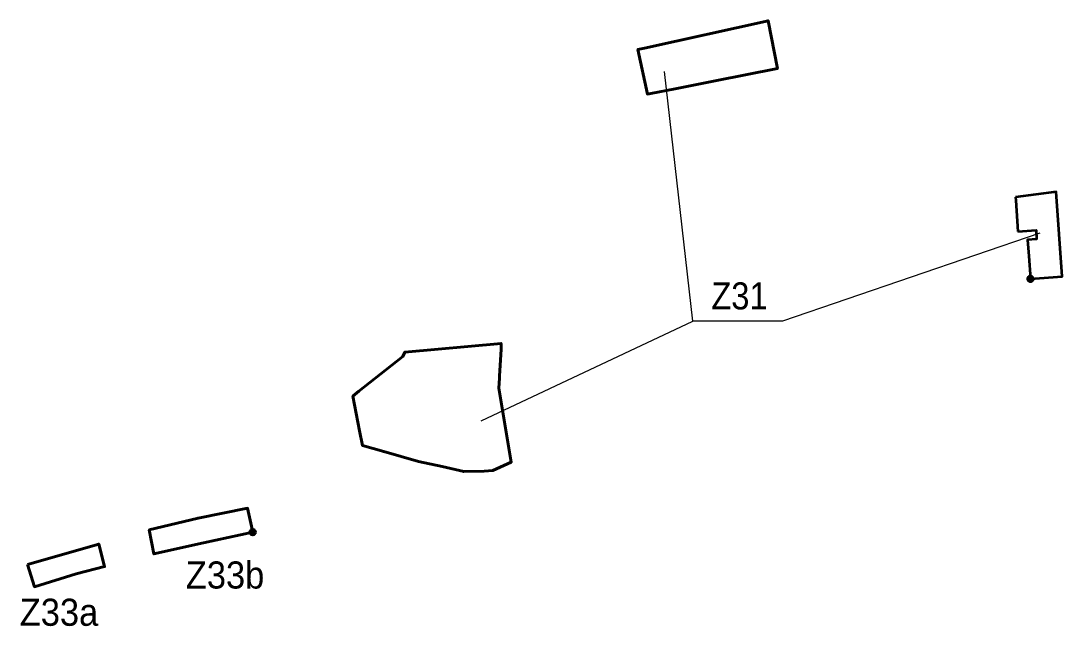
# Model space of a CAD drawing. Extents: x -650277 to -643422, y -1073980 to -1066720.
# Drawn here: x -644344 to -643422, y -1070237 to -1069701 of the extents above; entities that cross this region are included whole.
import ezdxf

# ---------------------------------------------------------------- set-up
doc = ezdxf.new("R2010")
doc.units = 0
doc.header["$LTSCALE"] = 9.6
doc.header["$PDMODE"] = 32
doc.header["$PDSIZE"] = 4.8
for name, color, linetype, lineweight in [('1', 7, 'Continuous', 60), ('3', 7, 'Continuous', 60), ('5', 7, 'Continuous', 60), ('63', 7, 'Continuous', 25), ('8', 7, 'Continuous', 60)]:
    doc.layers.add(name, color=color, linetype=linetype, lineweight=lineweight)

msp = doc.modelspace()

# ---------------------------------------------------------------- linework, layer by layer
at = {"layer": '1', "lineweight": 53}
for points in [[(-643450.3, -1069929.7), (-643422.204, -1069927.68), (-643427.6, -1069852.59), (-643463.51, -1069857.44)], [(-643463.51, -1069857.44), (-643463.31, -1069860.18), (-643461.327, -1069887.84)], [(-643461.327, -1069887.84), (-643445.37, -1069886.7), (-643444.79, -1069894.68), (-643452.77, -1069895.25), (-643451.74, -1069909.63), (-643450.3, -1069929.7)]]:
    msp.add_lwpolyline(points, dxfattribs=at)
at = {"layer": '1'}
msp.add_point((-643450.3, -1069929.7), dxfattribs=at)
at = {"layer": '3'}
for points in [[(-643791.88, -1069725.25), (-643797.75, -1069726.51), (-643789.3, -1069766.05), (-643786.35, -1069765.46), (-643764.94, -1069761.27), (-643729.34, -1069754.3), (-643674.3, -1069743.53), (-643682.61, -1069701.16)], [(-643920.84, -1070026.46), (-643920.29, -1070017.73), (-643920.16, -1070015.69), (-643918.69, -1069992.23), (-643918.88, -1069986.82), (-644004.06, -1069994.59), (-644005.92, -1069998.62), (-644044.7, -1070029.04), (-644050.12, -1070033.64), (-644044.18, -1070064.43), (-644041.71, -1070077.29), (-644022.77, -1070082.66), (-643991.99, -1070091.37), (-643971.03, -1070095.79), (-643951.99, -1070100.35), (-643933.96, -1070100.18), (-643926.33, -1070099.5), (-643909.87, -1070091.95)]]:
    msp.add_lwpolyline(points, close=True, dxfattribs=at)
at = {"layer": '5'}
msp.add_lwpolyline([(-644338.06, -1070182.64), (-644331.9, -1070202.4), (-644295.01, -1070190.9), (-644269.84, -1070184.57), (-644275.05, -1070164.59)], close=True, dxfattribs=at)
at = {"layer": '63'}
for p, q in [((-643749.085, -1069967.17), (-643774.294, -1069746.101)), ((-643936.672, -1070055.449), (-643749.085, -1069967.17))]:
    msp.add_line(p, q, dxfattribs=at)
msp.add_lwpolyline([(-643442.122, -1069889.276), (-643669.749, -1069967.17), (-643749.085, -1069967.17)], dxfattribs=at)
at = {"layer": '8'}
for p, q in [((-644138.78, -1070154.07), (-644143.31, -1070132.95)), ((-644182.31, -1070163.66), (-644138.78, -1070154.07))]:
    msp.add_line(p, q, dxfattribs=at)
msp.add_lwpolyline([(-644143.31, -1070132.95), (-644143.31, -1070132.95), (-644143.31, -1070132.95), (-644187.11, -1070141.58), (-644230.4, -1070152.08), (-644226.23, -1070173.28), (-644182.31, -1070163.66)], dxfattribs=at)
msp.add_point((-644138.78, -1070154.07), dxfattribs=at)

# ---------------------------------------------------------------- texts
at = {"layer": '63'}
for s, width, p in [('Z31', 0.9, (-643732.773, -1069956.784)), ('Z33b', 0.95, (-644198, -1070204)), ('Z33a', 0.95, (-644345, -1070237))]:
    msp.add_text(s, height=24, dxfattribs=dict(at, width=width)).set_placement(p)

doc.saveas('drawing.dxf')
